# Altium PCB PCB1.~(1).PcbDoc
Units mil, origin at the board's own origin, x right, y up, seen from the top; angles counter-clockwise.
Board outline 4980 x 2750 mil, 2 copper layers (Top Layer, Bottom Layer); 145 components, 200 nets, 610 pads, 29 vias.
Unrouted connection lines stored in the file: 204.
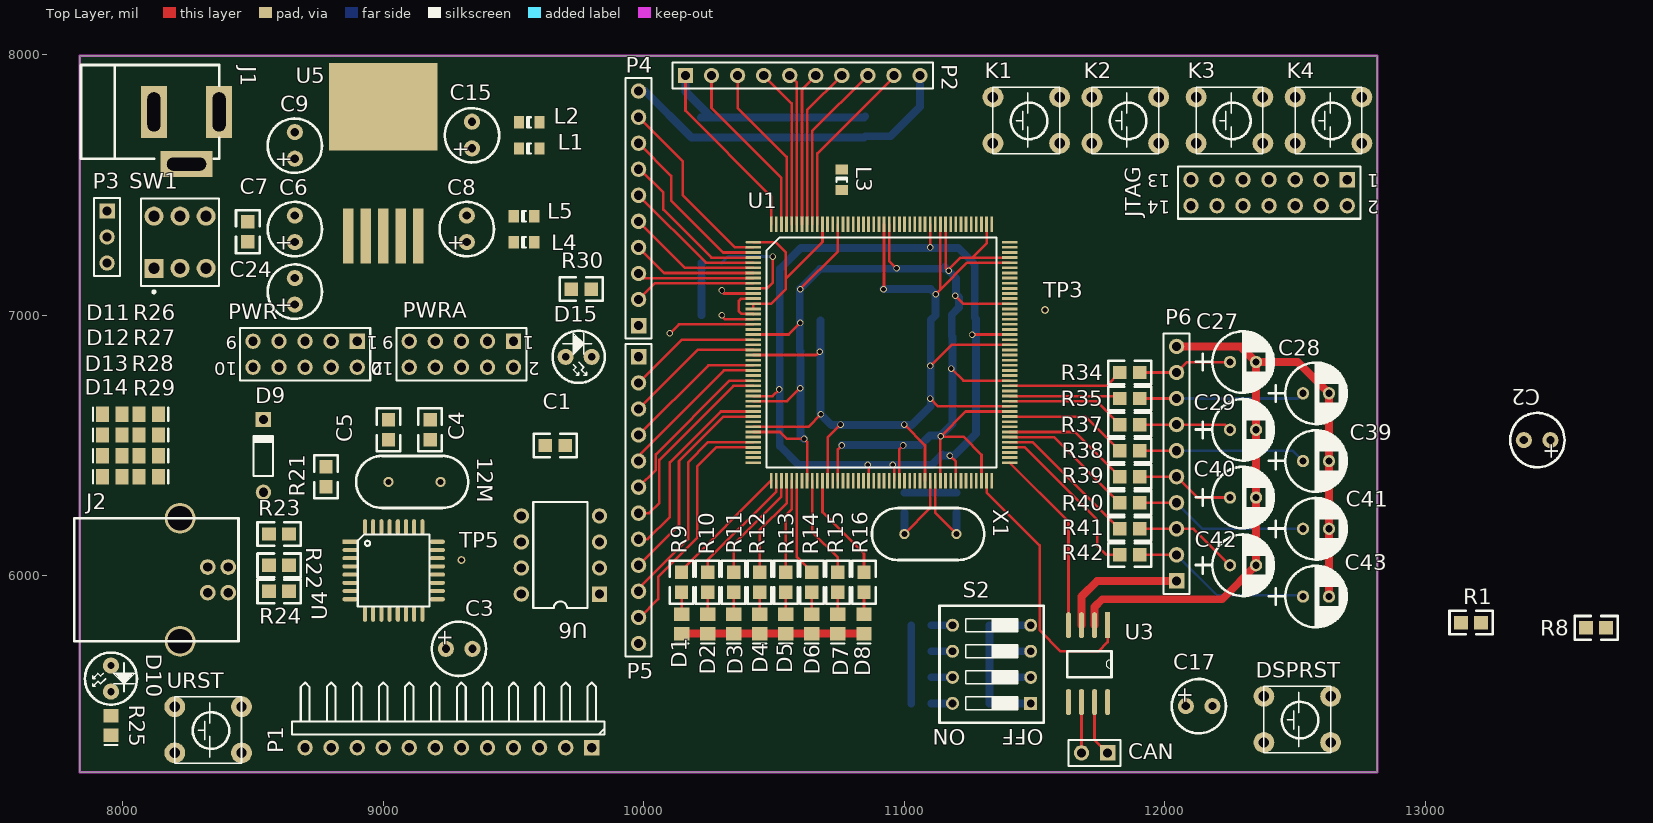
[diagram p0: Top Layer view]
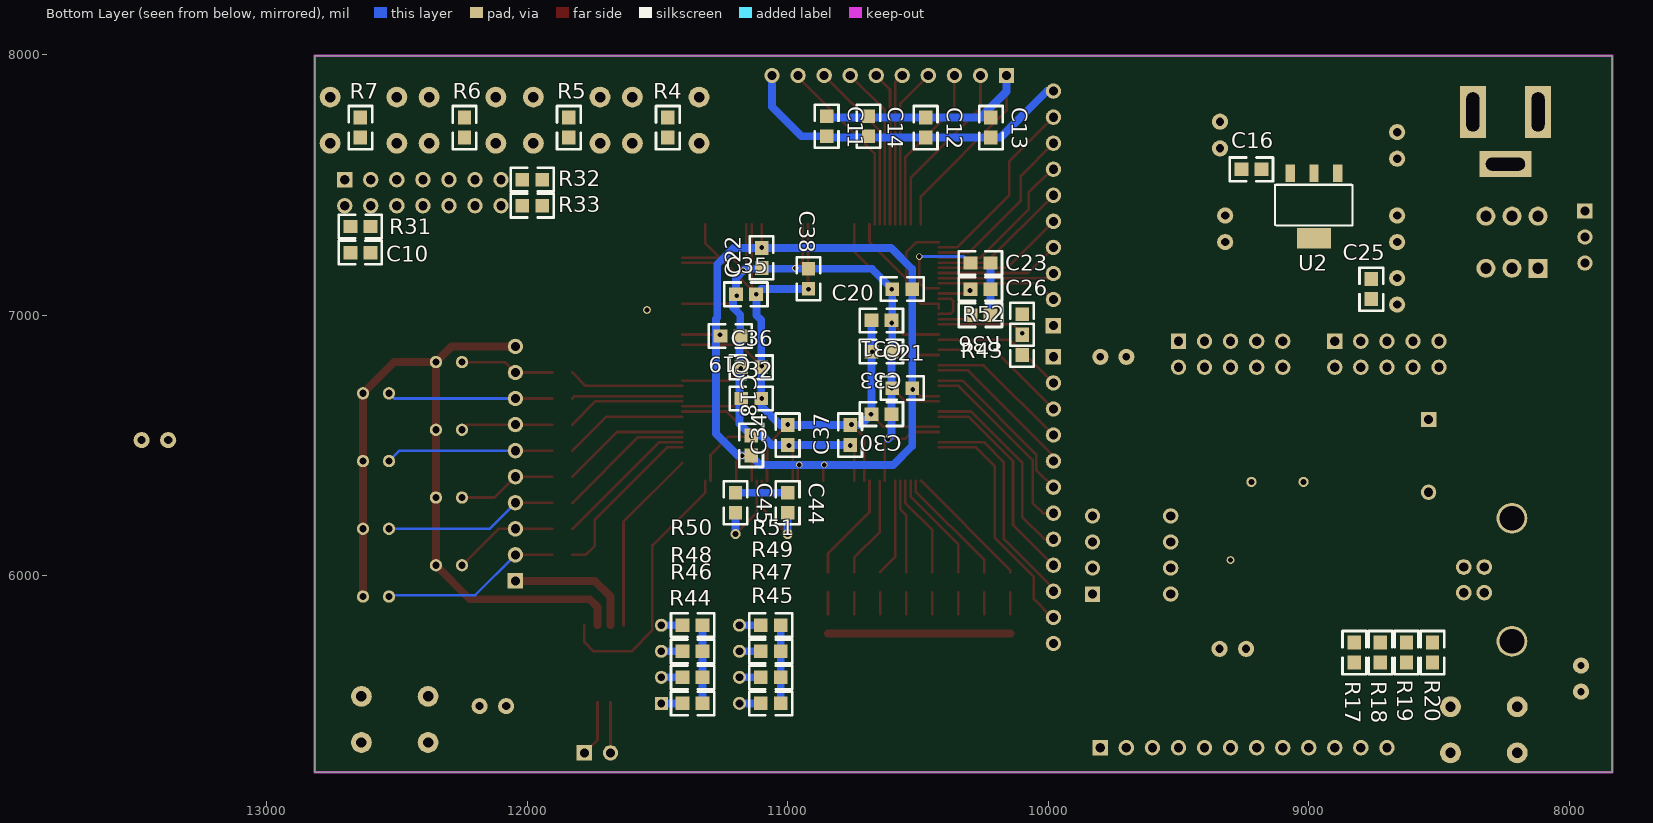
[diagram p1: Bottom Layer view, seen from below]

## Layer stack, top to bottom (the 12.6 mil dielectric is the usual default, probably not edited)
Top Layer: signal copper 1.4
Dielectric: core 12.6, FR-4, Dk 4.8
Bottom Layer: signal copper 1.4

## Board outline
7835,7995 7835,5245 12815,5245 12815,7995

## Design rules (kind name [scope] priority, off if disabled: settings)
Clearance [All] p1: gap=4
ComponentClearance [All] p1: gap=0 collisioncheckmode=3 verticalgap=0 showdistances=FALSE
HoleSize [All] p1: absolutevalues=TRUE maxlimit=1000 minlimit=0 maxpercent=80.000 minpercent=20.000
HoleToHoleClearance [All] p1: gap=1 allowstackedmicrovias=TRUE
MinimumSolderMaskSliver [All] p1: minsoldermaskwidth=2
PlaneClearance [All] p1: clearance=1
PlaneConnect [All] p1: planeconnectstyle=Direct reliefexpansion=20 reliefentries=4 reliefconductorwidth=10 reliefairgap=10
PolygonConnect [All] p1: connectstyle=Direct reliefconductorwidth=10 reliefentries=4 polygonreliefangle="90 Angle"
RoutingCorners [All] p1: cornerstyle=45-Degree minsetback=0 maxsetback=100
RoutingTopology [All] p1: topology=Horizontal
RoutingVias [All] p1: holewidth=18 width=25 viastyle="Through Hole" minholewidth=18 minwidth=25 maxholewidth=18 maxwidth=25
SilkToSilkClearance [All] p1: silktosilkclearance=0
SilkscreenOverComponentPads [All] p1: minsilkscreentomaskgap=0
SolderMaskExpansion [All] p1: expansion=2
TestPointUsage [All] p1: valid=0 allowmultiple=FALSE
Testpoint [All] p1: side=15 testpointundercomponent=TRUE minsize=40 maxsize=100 preferedsize=60 minholesize=0 maxholesize=40 preferedholesize=32 testpointgrid=1 style=1021 order=0-112345678
Width [All] p1: maxlimit=50 minlimit=10 preferedwidth=20
14 further rules are at their usual default settings.

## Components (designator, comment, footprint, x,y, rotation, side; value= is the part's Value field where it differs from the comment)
12M "XTAL" GJA-M 9120,6360 r0 top
C1 "Cap" C0805#1 9660,6500 r0 top
C2 "Cap Pol1" C5.3 13480,6520 r180 top
C3 "Cap Pol1" C5.3 9240,5720 r0 top
C4 "Cap" C0805#1 9180,6560 r90 top
C5 "Cap" C0805#1 9020,6560 r90 top
C6 "Cap Pol1" C5.3 8660,7280 r90 top
C7 "Cap" C0805#1 8480,7320 r270 top
C8 "Cap Pol1" C5.3 9320,7280 r90 top
C9 "Cap Pol1" C5.3 8660,7600 r90 top
C10 "Cap" C0805#1 12640,7240 r180 bottom
C11 "Cap" C0805#1 10850,7725 r270 bottom
C12 "Cap" C0805#1 10470,7720 r270 bottom
C13 "Cap" C0805#1 10220,7720 r270 bottom
C14 "Cap" C0805#1 10690,7725 r270 bottom
C15 "Cap Pol1" C5.3 9340,7640 r90 top
C16 "Cap" C0805#1 9220,7560 r180 bottom
C17 "Cap Pol1" C5.3 12080,5500 r0 top
C18 "Cap" C0805#1 11140,6500 r270 bottom
C19 "Cap" C0805#1 11220,6920 r0 bottom
C20 "Cap" C0805#1 10560,7100 r180 bottom
C21 "Cap" C0805#1 10560,6720 r180 bottom
C22 "Cap" C0805#1 11100,7220 r90 bottom
C23 "Cap" C0805#1 10260,7200 r180 bottom
C24 "Cap Pol1" C5.3 8660,7040 r90 top
C25 "Cap" C0805#1 8760,7100 r270 bottom
C26 "Cap" C0805#1 10260,7100 r180 bottom
C27 "Cap Pol2" CE2/6/.5 12300,6820 r90 top
C28 "Cap Pol2" CE2/6/.5 12580,6700 r90 top
C29 "Cap Pol2" CE2/6/.5 12300,6560 r90 top
C30 "Cap" C0805#1 10640,6620 r0 bottom
C31 "Cap" C0805#1 10640,6980 r0 bottom
C32 "Cap" C0805#1 11140,6680 r180 bottom
C33 "Cap" C0805#1 10640,6860 r0 bottom
C34 "Cap" C0805#1 11000,6540 r90 bottom
C35 "Cap" C0805#1 11160,7080 r180 bottom
C36 "Cap" C0805#1 11140,6800 r180 bottom
C37 "Cap" C0805#1 10760,6540 r90 bottom
C38 "Cap" C0805#1 10920,7140 r270 bottom
C39 "Cap Pol2" CE2/6/.5 12580,6440 r90 top
C40 "Cap Pol2" CE2/6/.5 12300,6300 r90 top
C41 "Cap Pol2" CE2/6/.5 12580,6180 r90 top
C42 "Cap Pol2" CE2/6/.5 12300,6040 r90 top
C43 "Cap Pol2" CE2/6/.5 12580,5920 r90 top
C44 "Cap" C0805#1 11000,6280 r270 bottom
C45 "Cap" C0805#1 11200,6280 r270 bottom
CAN "Header 2" HDR1X2 11780,5320 r180 top
D1 "LED1" C0805#2 10145,5815 r90 top
D2 "LED1" C0805#2 10245,5815 r90 top
D3 "LED1" C0805#2 10345,5815 r90 top
D4 "LED1" C0805#2 10445,5815 r90 top
D5 "LED1" C0805#2 10545,5815 r90 top
D6 "LED1" C0805#2 10645,5815 r90 top
D7 "LED1" C0805#2 10745,5815 r90 top
D8 "LED1" C0805#2 10845,5815 r90 top
D9 "1N4148" DO-35 8540,6460 r90 top
D10 "LED1" LED 7955,5655 r270 top
D11 "LED1" C0805#2 7960,6620 r0 top
D12 "LED1" C0805#2 7960,6540 r0 top
D13 "LED1" C0805#2 7960,6460 r0 top
D14 "LED1" C0805#2 7960,6380 r0 top
D15 "LED1" LED 9700,6840 r0 top
DSPRST "Button" SW-6 12380,5360 r0 top
J1 "PWR2.5" DCJACK 8120,7780 r0 top
J2 "USB_B_Female" USB_B_Female 8220,5980 r0 top
JTAG "JTAG14" HDR2X7 12700,7520 r180 top
K1 "Button" SW-6 11340,7660 r0 top
K2 "Button" SW-6 11720,7660 r0 top
K3 "Button" SW-6 12120,7660 r0 top
K4 "Button" SW-6 12500,7660 r0 top
L1 "Inductor" 2029 9560,7640 r0 top
L2 "Inductor" 2029 9560,7740 r0 top
L3 "Inductor" 2029 10760,7520 r270 top
L4 "Inductor" 2029 9540,7280 r0 top
L5 "Inductor" 2029 9540,7380 r0 top
P1 "Header 12H" HDR1X12H 9800,5340 r180 top
P2 "Header 10" HDR1X10 10160,7920 r0 top
P3 "Header 3" HDR1X3 7940,7400 r270 top
P4 "Header 10" HDR1X10 9980,6960 r90 top
P5 "Header 12" HDR1X12 9980,6840 r270 top
P6 "Header 10" HDR1X10 12045,5980 r90 top
PWR "Header 5X2" HDR2X5 8900,6900 r180 top
PWRA "Header 5X2" HDR2X5 9500,6900 r180 top
R1 "Res2" c0805 13175,5820 r0 top
R4 "Res2" c0805 11460,7720 r90 bottom
R5 "Res2" c0805 11840,7720 r90 bottom
R6 "Res2" c0805 12240,7720 r90 bottom
R7 "Res2" c0805 12640,7720 r270 bottom
R8 "Res2" c0805 13655,5800 r0 top
R9 "Res2" c0805 10145,5975 r270 top
R10 "Res2" c0805 10245,5975 r270 top
R11 "Res2" c0805 10345,5975 r270 top
R12 "Res2" c0805 10445,5975 r270 top
R13 "Res2" c0805 10545,5975 r270 top
R14 "Res2" c0805 10645,5975 r270 top
R15 "Res2" c0805 10745,5975 r270 top
R16 "Res2" c0805 10845,5975 r270 top
R17 "Res2" c0805 8825,5705 r270 bottom
R18 "Res2" c0805 8725,5705 r270 bottom
R19 "Res2" c0805 8625,5705 r270 bottom
R20 "Res2" c0805 8525,5705 r270 bottom
R21 "Res2" c0805 8780,6380 r90 top
R22 "Res2" c0805 8600,6040 r180 top
R23 "Res2" c0805 8600,6160 r180 top
R24 "Res2" c0805 8600,5940 r180 top
R25 "Res1" C0805#2 7955,5425 r90 top
R26 "Res1" C0805#2 8100,6620 r180 top
R27 "Res1" C0805#2 8100,6540 r180 top
R28 "Res1" C0805#2 8100,6460 r180 top
R29 "Res1" C0805#2 8100,6380 r180 top
R30 "Res2" c0805 9760,7100 r0 top
R31 "Res2" c0805 12640,7340 r0 bottom
R32 "Res2" c0805 11980,7520 r0 bottom
R33 "Res2" c0805 11980,7420 r0 bottom
R34 "Res2" c0805 11865,6780 r0 top
R35 "Res2" c0805 11865,6680 r0 top
R36 "Res2" c0805 10260,7000 r0 bottom
R37 "Res2" c0805 11865,6580 r0 top
R38 "Res2" c0805 11865,6480 r0 top
R39 "Res2" c0805 11865,6380 r0 top
R40 "Res2" c0805 11865,6280 r0 top
R41 "Res2" c0805 11865,6180 r0 top
R42 "Res2" c0805 11865,6080 r0 top
R43 "Res2" c0805 10100,6885 r270 bottom
R44 "Res2" c0805 11365,5510 r0 bottom
R45 "Res2" c0805 11065,5510 r180 bottom
R46 "Res2" c0805 11365,5610 r0 bottom
R47 "Res2" c0805 11065,5610 r180 bottom
R48 "Res2" c0805 11365,5710 r0 bottom
R49 "Res2" c0805 11065,5710 r180 bottom
R50 "Res2" c0805 11365,5810 r0 bottom
R51 "Res2" c0805 11065,5810 r180 bottom
R52 "Res2" c0805 10100,6965 r270 bottom
S2 "SW SO8" SW-DIP2x4 11485,5510 r180 top
SW1 "SWITCH" DPDT-6 8220,7280 r90 top
TP3 "TestPoint" TESTPOINT 11540,7020 r90 top
TP5 "TestPoint" TESTPOINT 9300,6060 r90 top
U1 "TMS320F2812" Quad176_2812 10420,7280 r0 top
U2 "AS1117-1.8" SOT-223 8980,7420 r0 bottom
U3 "SN65HVD232" SOP8 11720,5660 r270 top
U4 "TUSB3410" DMC68HC908JL8 9040,6020 r90 top
U5 "TPS78633" PSFM_G5 9000,7800 r0 top
U6 "24LCxx" DIP-8 9680,6080 r90 top
URST "Button" SW-6 8200,5320 r0 top
X1 "30MHz" GJA-M 11100,6160 r0 top

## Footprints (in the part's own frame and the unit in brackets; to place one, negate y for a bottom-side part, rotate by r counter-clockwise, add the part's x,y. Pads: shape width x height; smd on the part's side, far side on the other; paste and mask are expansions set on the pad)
2029 [mm] "Chip Inductor; Body 2 x 1.2 mm (LxW typ)"
  rect 1x1.2 smd: 1(-1,0) 2(1,0)
  silkscreen extent -0.2,-0.5 0.2,0.5
C5.3 [mil]
  round 62 hole 31.5: 1(0.39,-0.55) 2(102.39,-0.55)
  silkscreen extent -54,-105 155,104
C0805#1 [mm]
  rect 1.35x1.3 smd: 1(-0.975,0) 2(0.975,0)
  silkscreen extent -2.1,-1.15 2.1,1.15
C0805#2 [mm] "Chip Capacitor; Body 2.0 x 1.2 mm (LxW typ)"
  rect 1.3x1.5 smd: 1(-0.95,0) 2(0.95,0)
  silkscreen extent -1.9,-0.65 -1.9,0.65
c0805 [mm]
  rect 1.35x1.3 smd: 1(-0.975,0) 2(0.975,0)
  silkscreen extent -2.1,-1.15 2.1,1.15
CE2/6/.5 [mm]
  round 1.2 hole 0.7: 1(0,1.27) 2(0,-1.27)
  silkscreen extent -3,-3 3,4.62
DCJACK [mil]
  rect 100x200 hole 50 slot 150 at 90 deg: 1(0,0) 2(250,0)
  rect 200x100 hole 50 slot 150 at 0 deg: 3(125,-200)
  silkscreen extent -280,-180 250,180
DIP-8 [mm]
  rect 1.5x1.5 hole 0.9: 1(-3.822,-3.81)
  round 1.5 hole 0.9: 2(-1.282,-3.81) 3(1.258,-3.81) 4(3.798,-3.81) 5(3.798,3.81) 6(1.258,3.81) 7(-1.282,3.81) 8(-3.822,3.81)
  silkscreen extent -5.16,-2.65 5.14,2.65
DMC68HC908JL8 [mm]
  rect 0.4x1.5 smd: 1(2.8,4.25)
  oval 0.4x1.5 smd: 2(2,4.25) 3(1.2,4.25) 4(0.4,4.25) 5(-0.4,4.25) 6(-1.2,4.25) 7(-2,4.25) 8(-2.8,4.25) 17(-2.8,-4.25) 18(-2,-4.25) 19(-1.2,-4.25) 20(-0.4,-4.25) 21(0.4,-4.25) 22(1.2,-4.25) 23(2,-4.25) 24(2.8,-4.25)
  oval 1.5x0.4 smd: 9(-4.25,2.8) 10(-4.25,2) 11(-4.25,1.2) 12(-4.25,0.4) 13(-4.25,-0.4) 14(-4.25,-1.2) 15(-4.25,-2) 16(-4.25,-2.8) 25(4.25,-2.8) 26(4.25,-2) 27(4.25,-1.2) 28(4.25,-0.4) 29(4.25,0.4) 30(4.25,1.2) 31(4.25,2) 32(4.25,2.8)
  silkscreen extent -3.5,-3.5 3.5,3.5
DO-35 [mm] "Diode, Axial; Body 3.8 x 1.9 mm (LxDia. max), Lead Dia. 0.53 mm (max)"
  round 1.5 hole 0.9: 1(-3.55,0)
  rect 1.5x1.5 hole 0.9: 2(3.55,0)
  silkscreen extent -1.95,-0.95 2.05,0.95
DPDT-6 [mm] "Double-Pole, Double-Throw Switch; 6 Leads"
  rect 1.85x1.85 hole 1.1: 1(-2.54,2.54)
  round 1.85 hole 1.1: 2(-2.54,0) 3(-2.54,-2.54) 4(2.54,-2.54) 5(2.54,0) 6(2.54,2.54)
  silkscreen extent -4.96,-3.81 4.28,3.81
GJA-M [mm]
  round 1 hole 0.6: 1(-2.54,0) 2(2.54,0)
  silkscreen extent -5.69,-2.54 5.23,2.54
HDR1X2 [mm] "Connector; Header; 2 Position"
  rect 1.5x1.5 hole 0.9: 1(0,0)
  round 1.5 hole 0.9: 2(2.54,0)
  silkscreen extent -1.27,-1.27 3.81,1.27
HDR1X3 [mm] "Connector; Header; 3 Position"
  rect 1.5x1.5 hole 0.9: 1(0,0)
  round 1.5 hole 0.9: 2(2.54,0) 3(5.08,0)
  silkscreen extent -1.27,-1.27 6.35,1.27
HDR1X10 [mm] "Connector; Header; 10 Position"
  rect 1.5x1.5 hole 0.9: 1(0,0)
  round 1.5 hole 0.9: 2(2.54,0) 3(5.08,0) 4(7.62,0) 5(10.16,0) 6(12.7,0) 7(15.24,0) 8(17.78,0) 9(20.32,0) 10(22.86,0)
  silkscreen extent -1.27,-1.27 24.13,1.27
HDR1X12 [mm] "Connector; Header; 12 Position"
  rect 1.5x1.5 hole 0.9: 1(0,0)
  round 1.5 hole 0.9: 2(2.54,0) 3(5.08,0) 4(7.62,0) 5(10.16,0) 6(12.7,0) 7(15.24,0) 8(17.78,0) 9(20.32,0) 10(22.86,0) 11(25.4,0) 12(27.94,0)
  silkscreen extent -1.27,-1.27 29.21,1.27
HDR1X12H [mm] "Connector; Header; 12 Position; Right Angle"
  rect 1.5x1.5 hole 0.9: 1(0,0)
  round 1.5 hole 0.9: 2(2.54,0) 3(5.08,0) 4(7.62,0) 5(10.16,0) 6(12.7,0) 7(15.24,0) 8(17.78,0) 9(20.32,0) 10(22.86,0) 11(25.4,0) 12(27.94,0)
  silkscreen extent -1.27,-6.35 29.21,-1.27
HDR2X5 [mm] "Connector; Header; 5x2 Position"
  rect 1.5x1.5 hole 0.9: 1(0,0)
  round 1.5 hole 0.9: 2(0,2.54) 3(2.54,0) 4(2.54,2.54) 5(5.08,0) 6(5.08,2.54) 7(7.62,0) 8(7.62,2.54) 9(10.16,0) 10(10.16,2.54)
  silkscreen extent -1.27,-1.27 11.43,3.81
HDR2X7 [mm] "Connector; Header; 7x2 Position"
  rect 1.5x1.5 hole 0.9: 1(0,0)
  round 1.5 hole 0.9: 2(0,2.54) 3(2.54,0) 4(2.54,2.54) 5(5.08,0) 6(5.08,2.54) 7(7.62,0) 8(7.62,2.54) 9(10.16,0) 10(10.16,2.54) 11(12.7,0) 12(12.7,2.54) 13(15.24,0) 14(15.24,2.54)
  silkscreen extent -1.27,-1.27 16.51,3.81
LED [mil]
  round 62 hole 28: 1(0,0) 2(100,0)
  silkscreen extent -50,-100 150,100
PSFM_G5 [mm]
  rect 1x5.4 smd: 1(-3.4,-12.6) 2(-1.7,-12.6) 3(0,-12.6) 4(1.7,-12.6) 5(3.4,-12.6)
  rect 10.6x8.5 smd: 6(0,0)
Quad176_2812 [mm]
  oval 1.5x0.27 smd: 1(0,0)
  rect 1.5x0.27 smd: 2(0,-0.5) 3(0,-1) 4(0,-1.5) 5(0,-2) 6(0,-2.5) 7(0,-3) 8(0,-3.5) 9(0,-4) 10(0,-4.5) 11(0,-5) 12(0,-5.5) 13(0,-6) 14(0,-6.5) 15(0,-7) 16(0,-7.5) 17(0,-8) 18(0,-8.5) 19(0,-9) 20(0,-9.5) 21(0,-10) 22(0,-10.5) 23(0,-11) 24(0,-11.5) 25(0,-12) 26(0,-12.5) 27(0,-13) 28(0,-13.5) 29(0,-14) 30(0,-14.5) 31(0,-15) 32(0,-15.5) 33(0,-16) 34(0,-16.5) 35(0,-17) 36(0,-17.5) 37(0,-18) 38(0,-18.5) 39(0,-19) 40(0,-19.5) 41(0,-20) 42(0,-20.5) 43(0,-21) 44(0,-21.5) 89(25,-21.5) 90(25,-21) 91(25,-20.5) 92(25,-20) 93(25,-19.5) 94(25,-19) 95(25,-18.5) 96(25,-18) 97(25,-17.5) 98(25,-17) 99(25,-16.5) 100(25,-16) 101(25,-15.5) 102(25,-15) 103(25,-14.5) 104(25,-14) 105(25,-13.5) 106(25,-13) 107(25,-12.5) 108(25,-12) 109(25,-11.5) 110(25,-11) 111(25,-10.5) 112(25,-10) 113(25,-9.5) 114(25,-9) 115(25,-8.5) 116(25,-8) 117(25,-7.5) 118(25,-7) 119(25,-6.5) 120(25,-6) 121(25,-5.5) 122(25,-5) 123(25,-4.5) 124(25,-4) 125(25,-3.5) 126(25,-3) 127(25,-2.5) 128(25,-2) 129(25,-1.5) 130(25,-1) 131(25,-0.5) 132(25,0)
  rect 0.27x1.5 smd: 45(1.75,-23.25) 46(2.25,-23.25) 47(2.75,-23.25) 48(3.25,-23.25) 49(3.75,-23.25) 50(4.25,-23.25) 51(4.75,-23.25) 52(5.25,-23.25) 53(5.75,-23.25) 54(6.25,-23.25) 55(6.75,-23.25) 56(7.25,-23.25) 57(7.75,-23.25) 58(8.25,-23.25) 59(8.75,-23.25) 60(9.25,-23.25) 61(9.75,-23.25) 62(10.25,-23.25) 63(10.75,-23.25) 64(11.25,-23.25) 65(11.75,-23.25) 66(12.25,-23.25) 67(12.75,-23.25) 68(13.25,-23.25) 69(13.75,-23.25) 70(14.25,-23.25) 71(14.75,-23.25) 72(15.25,-23.25) 73(15.75,-23.25) 74(16.25,-23.25) 75(16.75,-23.25) 76(17.25,-23.25) 77(17.75,-23.25) 78(18.25,-23.25) 79(18.75,-23.25) 80(19.25,-23.25) 81(19.75,-23.25) 82(20.25,-23.25) 83(20.75,-23.25) 84(21.25,-23.25) 85(21.75,-23.25) 86(22.25,-23.25) 87(22.75,-23.25) 88(23.25,-23.25) 133(23.25,1.75) 134(22.75,1.75) 135(22.25,1.75) 136(21.75,1.75) 137(21.25,1.75) 138(20.75,1.75) 139(20.25,1.75) 140(19.75,1.75) 141(19.25,1.75) 142(18.75,1.75) 143(18.25,1.75) 144(17.75,1.75) 145(17.25,1.75) 146(16.75,1.75) 147(16.25,1.75) 148(15.75,1.75) 149(15.25,1.75) 150(14.75,1.75) 151(14.25,1.75) 152(13.75,1.75) 153(13.25,1.75) 154(12.75,1.75) 155(12.25,1.75) 156(11.75,1.75) 157(11.25,1.75) 158(10.75,1.75) 159(10.25,1.75) 160(9.75,1.75) 161(9.25,1.75) 162(8.75,1.75) 163(8.25,1.75) 164(7.75,1.75) 165(7.25,1.75) 166(6.75,1.75) 167(6.25,1.75) 168(5.75,1.75) 169(5.25,1.75) 170(4.75,1.75) 171(4.25,1.75) 172(3.75,1.75) 173(3.25,1.75) 174(2.75,1.75) 175(2.25,1.75) 176(1.75,1.75)
  silkscreen extent 1.28,-21.96 23.71,0.47
SOP8 [mil]
  rect 100x20 smd: 1(-150,60)
  oval 100x20 smd: 2(-150,10) 3(-150,-40) 4(-150,-90) 5(145,-90) 6(145,-40) 7(145,10) 8(145,60)
  silkscreen extent -50,-95 50,75
SOT-223 [mm]
  rect 0.9x1.7 smd: 1(-2.311,-3.162) 2(0,-3.162) 3(2.311,-3.162)
  rect 3.28x2 smd: 4(0,3.162)
  silkscreen extent -3.76,-2.07 3.78,1.92
SW-6 [mil]
  round 80 hole 40: 1(0,0) 2(0,177) 3(256,0) 4(256,177)
  silkscreen extent 0,-40 256,215
SW-DIP2x4 [mil]
  rect 50x50 hole 30: 1(0,0)
  round 50 hole 30: 2(0,-100) 3(0,-200) 4(0,-300) 5(300,-300) 6(300,-200) 7(300,-100) 8(300,0)
  silkscreen extent -50,-375 350,75
TESTPOINT [mil]
  round 30 hole 20: 1(0,0)
USB_B_Female [mil]
  round 60 hole 36.22: 1(185,-45) 2(185,53.42) 3(106.26,53.42) 4(106.26,-45)
  round 118.11 hole 94.49: 5(-0.04,240.43) 6(-0.04,-232.01)
  silkscreen extent -406,-232 224,240

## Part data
12M: "Crystal Oscillator"
C1 C5: library part "Cap Pol1", "Polarized Capacitor (Radial)"
C2 C6 C8 C27 C28 C29 C39: library part Cap, "Capacitor"
C3 C15 C17 C24: "Polarized Capacitor (Radial)"
C4 C7 C10 C11 C12 C13 C14 C16 C18 C19 C20 C21 C22 C23 C25 C26 C30 C31 C32 C33 C34 C35 C36 C37 C38 C44 C45: "Capacitor"
C9: library part CAP, "Capacitor"
C40 C41 C42 C43: "Polarized Capacitor (Axial)"
CAN: "Header, 2-Pin"
D1 D2 D3 D4 D5 D6 D7 D8 D10 D11 D12 D13 D14 D15: "Typical RED GaAs LED"
D9: library part "Diode 1N4148", "High Conductance Fast Diode"
DSPRST K1 K2 K3 K4 URST: library part Button_4
J1: "Low Voltage Power Supply Connector"
JTAG: library part "Header 7X2", "Header, 7-Pin, Dual row"
P1: "Header, 12-Pin, Right Angle"
P2 P4 P6: "Header, 10-Pin"
P3: "Header, 3-Pin"
P5: library part "Header 8", "Header, 8-Pin"
PWR PWRA: "Header, 5-Pin, Dual row"
R1 R4 R5 R6 R9 R10 R11 R12 R13 R14 R15 R16 R17 R18 R19 R20 R21 R22 R23 R24 R25 R26 R27 R28 R29 R30 R31 R32 R33 R34 R35 R36 R37 R38 R39 R40 R41 R42 R43 R44 R45 R46 R47 R48 R49 R50 R51 R52: "Resistor"
R7 R8: library part RES2
S2: library part "SW DIP-4", "DIP Switch"
SW1: library part SW-DPDT
TP3 TP5: "TespPoint"
U2: library part TPS767D318
U3: "CAN transmiceiver"
U5: library part CY7C1041V33
U6: library part MAX3232
X1: library part CRYSTAL

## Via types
v1: diameter 25, hole 18, Top Layer to Bottom Layer, 29 vias

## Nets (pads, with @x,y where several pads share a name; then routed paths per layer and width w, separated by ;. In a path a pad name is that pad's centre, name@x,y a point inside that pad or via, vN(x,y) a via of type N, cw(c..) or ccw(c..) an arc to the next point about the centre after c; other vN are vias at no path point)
+1.8: C30.2 C31.2 C32.2 C33.2 C34.2 C35.2 C36.2 C37.2 C38.2 L3.1 U1.23 U1.37 U1.56 U1.75 U1.100 U1.112 U1.128 U1.143 U1.154 | length 3991.9
  Top Layer w10: U1.37 10631.34,6571.34 v1(10680,6620) ; U1.23 10661.93,6846.93 v1(10675,6860) ; U1.56 10705.43,6530.43 v1(10755,6580) ; v1(10920,7100) 10921.97,7101.97 U1.154 ; v1(11000,6580) 11079.45,6500.55 U1.75 ; v1(11100,6680) 11129.92,6650.08 U1.100 ; v1(11100,6805) 11181.3,6886.3 U1.112 ; v1(11120,7080) 11138.5,7098.5 ; U1.143 11138.5,7098.5 ; U1.128 11241.26,7201.26 11138.5,7098.5
  Bottom Layer w30: C31.2 C33.2 C30.2 10720,6578.39 11028.39,6578.39 11101.61,6651.61 11101.61,6981.61 11120,7000 11120,7078.39 C35.2 11101.61,7100 10921.61,7100 C38.2
+1.8V: C24.1 C25.2 U2.2 U2.4 U4.4
+3.3: C1.2 C8.1 C15.1 C16.2 D11.1 D12.1 D13.1 D14.1 L1.1 L4.1 P1.1 R17.2 R18.2 R19.2 R20.2 R30.1 U2.3 U4.3 U4.23 U4.24 U4.25 U5.4 U6.8
+5: C6.1 C7.2 SW1.1 SW1.6 U5.1 U5.2
ADA0: P2.2 U1.174 | length 682.2
  Top Layer w10: P2.2 10260,7795 10528.27,7526.73 U1.174
ADA1: P2.3 U1.173 | length 649
  Top Layer w10: P2.3 10360,7795 10547.95,7607.05 U1.173
ADA2: P2.4 U1.172 | length 615.7
  Top Layer w10: P2.4 10567.64,7812.36 U1.172
ADA3: P2.5 U1.171 | length 582.4
  Top Layer w10: P2.5 10587.32,7892.68 U1.171
ADA4: P2.6 U1.170 | length 593.1
  Top Layer w10: U1.170 10607.01,7867.01 P2.6
ADA5: P2.7 U1.169 | length 626.3
  Top Layer w10: U1.169 10626.69,7786.69 P2.7
ADA6: P2.8 U1.168 | length 659.6
  Top Layer w10: U1.168 10646.38,7706.38 P2.8
ADA7: P2.9 U1.167 | length 692.9
  Top Layer w10: U1.167 10666.06,7621.06 10960,7915 P2.9
ADB0: P4.9 U1.2 | length 723.1
  Top Layer w10: P4.9 10012.5,7727.5 10150,7590 10150,7460 10349.68,7260.32 U1.2
ADB1: P4.8 U1.3 | length 669.4
  Top Layer w10: P4.8 10105,7535 10105,7440 10304.37,7240.63 U1.3
ADB2: P4.7 U1.4 | length 618.5
  Top Layer w10: P4.7 9985,7560 10075,7470 10075,7405 10259.05,7220.95 U1.4
ADB3: P4.6 U1.5 | length 547.2
  Top Layer w10: P4.6 10238.74,7201.26 U1.5
ADB4: P4.5 U1.6 | length 513.9
  Top Layer w10: P4.5 10158.42,7181.58 U1.6
ADB5: P4.4 U1.7 | length 480.6
  Top Layer w10: P4.4 10078.11,7161.89 U1.7
ADB6: P4.3 U1.8 | length 447.4
  Top Layer w10: P4.3 9997.79,7142.21 U1.8
ADB7: P4.2 U1.9 | length 465.9
  Top Layer w10: P4.2 10042.52,7122.52 U1.9
CTS: P1.9 U4.13
DA1: C43.1 P6.2 R42.2 | length 692.9
  Top Layer w10: R42.2 P6.2
  Bottom Layer w10: P6.2 12200,5925 12525,5925 C43.1
DA2: C42.1 P6.3 R41.2 | length 404.6
  Top Layer w10: R41.2 P6.3 12110,6180 C42.1
DA3: C41.1 P6.4 R40.2 | length 668
  Top Layer w10: R40.2 P6.4
  Bottom Layer w10: P6.4 12145,6180 C41.1
DA4: C40.1 P6.5 R39.2 | length 379.8
  Top Layer w10: R39.2 P6.5 12125,6300 C40.1
DA5: C39.1 P6.6 R38.2 | length 643.2
  Top Layer w10: R38.2 P6.6
  Bottom Layer w10: P6.6 12490,6480 C39.1
DA6: C29.1 P6.7 R37.2 | length 354.9
  Top Layer w10: R37.2 P6.7 12230,6580 C29.1
DA7: C28.1 P6.8 R35.2 | length 634.9
  Top Layer w10: R35.2 P6.8
  Bottom Layer w10: P6.8 12510,6680 C28.1
DA8: C27.1 P6.9 R34.2 | length 363.2
  Top Layer w10: R34.2 P6.9 12085,6820 C27.1
DCD: P1.7 U4.15
DSP_VDD: C17.1 C18.2 C19.2 C20.2 C21.2 C22.2 D1.1 D2.1 D3.1 D4.1 D5.1 D6.1 D7.1 D8.1 JTAG.5 L1.2 P5.1 P6.1 PWR.1 PWR.3 PWR.5 PWR.7 PWR.9 R1.2 R4.2 R5.2 R6.2 R7.2 R32.1 R33.1 U1.31 U1.64 U1.69 U1.81 U1.114 U1.145 U3.3 | length 4752.2
  Top Layer w10: U1.31 10494.45,6689.45 v1(10520,6715) ; v1(10860,6425) 10862.91,6422.09 U1.64 ; v1(10955,6425) 10955,6420 10961.34,6413.66 U1.69 ; U1.145 11099.13,7260.87 v1(11100,7260) ; v1(11175,6460) 11197.56,6437.44 U1.81 ; v1(11260,6925) 11260.67,6925.67 U1.114
  Top Layer w30: D1.1 D2.1 D3.1 D4.1 D5.1 D6.1 D7.1 D8.1 ; U3.3 11680,5920 11740,5980 P6.1
  Bottom Layer w30: C18.2 C18.2@11141.61,6461.61 ; C18.2@11145,6465 C18.2@11141.61,6461.61 ; C18.2@11141.61,6461.61 11191.61,6461.61 11275,6545 11275,6985 11270,6990 11270,7195 11206.61,7258.39 C22.2 10820,7258.39 10603.39,7258.39 10521.61,7176.61 C20.2 C21.2 10521.61,6498.39 10595,6425 11105,6425 C18.2@11141.61,6461.61
DSP_VDDA: C11.2 C12.2 C13.2 C14.2 L4.2 P2.10 P4.10 PWRA.1 PWRA.3 PWRA.5 PWRA.7 PWRA.9 U1.1 U1.13 U1.14 U1.166 | length 2038.8
  Top Layer w10: U1.14 U1.13 10488.78,7043.78 10545,7100 10545,7140.9 ; U1.1 10505,7280 10545,7240 10545,7140.9 ; U1.166 10685.75,7281.64 10545,7140.9
  Bottom Layer w30: P4.10 10005,7860 10183.39,7681.61 C13.2 C12.2 10845,7681.61 C11.2 10946.61,7686.61 11060,7800 P2.10
DSP_VSS: C2.2 C10.2 C17.2 C18.1 C19.1 C20.1 C21.1 C22.1 C27.2 C28.2 C29.2 C30.1 C31.1 C32.1 C33.1 C34.1 C35.1 C36.1 C37.1 C38.1 C39.2 C40.2 C41.2 C42.2 C43.2 C44.1 C45.1 JTAG.4 JTAG.8 JTAG.10 JTAG.12 K1.2 K2.2 K3.2 K4.2 L2.2 P5.12 P6.10 PWR.2 PWR.4 PWR.6 PWR.8 PWR.10 R8.1 R31.1 U1.19 U1.32 U1.38 U1.52 U1.58 U1.70 U1.78 U1.86 U1.99 U1.105 U1.113 U1.120 U1.129 U1.134 U1.142 U1.153 U1.163 U3.2 | length 8802.7
  Top Layer w10: U1.38 10523.34,6551.66 10550,6525 v1(10615,6525) 10626.69,6513.31 U1.52 ; U1.32 10549.77,6669.77 v1(10600,6720) ; U1.19 10555.67,6925.67 v1(10600,6970) ; v1(10600,7100) 10744.8,7244.8 U1.163 ; U1.58 10744.8,6484.8 v1(10760,6500) ; U1.153 10941.65,7208.35 v1(10970,7180) ; U1.70 10981.02,6486.02 v1(10995,6500) ; U1.78 v1@11138.5,6533.5 ; U1.142 11158.19,7181.81 v1(11170,7170) v1@11170,7175.35 ; v1@11175,7180.35 11215.6,7220.95 11260.95,7220.95 ; v1(11180,6795) 11226.49,6748.51 U1.105 ; v1(11195,7075) 11226.22,7043.78 U1.120 ; U1.86 11295.98,6464.02 11226.5,6533.5 v1@11141.5,6533.5 ; U1.134 11315.67,7275.67 11260.95,7220.95 ; U1.99 11235.4,6630.4 v1(11140,6535) ; U1.129 11260.95,7220.95 ; v1@11138.5,6533.5 v1@11141.5,6533.5 ; v1@11138.5,6533.5 v1(11140,6535) ; v1(11140,6535) v1@11141.5,6533.5
  Top Layer w30: U3.2 11730,5880 11760,5910 12220,5910 C42.2 C40.2 C29.2 C27.2 ; P6.10 12290,6880 C27.2 ; C43.2 C41.2 C39.2 C28.2 12510,6820 C27.2
  Bottom Layer w30: v1(10615,6525) 10601.61,6538.39 C30.1 C33.1 10598.39,6863.23 C20.1 10676.77,7178.39 C38.1 11100,7178.39 11148.39,7178.39 11155,7185 v1(11170,7170) 11198.39,7141.61 C35.1 11210,7068.39 11210,7030 11181.61,7001.61 C19.1 11185,6916.61 11185,6583.39 C18.1 11098.39,6538.39 11061.61,6501.61 C34.1 C37.1 ; C44.1 C45.1
DSP_VSSA: C11.1 C12.1 C13.1 C14.1 C23.2 C26.2 L5.2 P2.1 P4.1 PWRA.2 PWRA.4 PWRA.6 PWRA.8 PWRA.10 R36.1 U1.12 U1.15 U1.165 U1.175 U1.176 | length 1900.3
  Top Layer w10: P2.1 10160,7785 10488.9,7456.1 U1.176 ; U1.15 10419.41,7005 10375,7005 10365,7015 10365,7055 10373.47,7063.47 U1.12
  Bottom Layer w30: P2.1 10160,7858.39 10260,7758.39 ; C13.1 10260,7758.39 ; R36.1 C26.2 C23.2 ; C11.1 10845,7758.39 C12.1 10260,7758.39
DSPVDD: R43.2 R44.1 R46.1 R48.1 R50.1 | length 300
  Bottom Layer w30: R44.1 R46.1 11326.61,5730 R50.1
DSPVSS: R45.2 R47.2 R49.2 R51.2 R52.1 | length 300
  Bottom Layer w30: R45.2 R47.2 R49.2 R51.2
DSR: P1.8 U4.14
DTR: P1.5 U4.21
EMU0: JTAG.13 R32.2 U1.137
EMU1: JTAG.14 R33.2 U1.146
GND: C1.1 C3.2 C4.2 C5.2 C6.2 C7.1 C8.2 C9.2 C15.2 C16.1 C24.2 C25.1 D15.2 J1.1 J2.4 L2.1 L5.1 P1.12 R25.1 U2.1 U4.8 U4.18 U4.28 U5.3 U5.6 U6.1 U6.2 U6.3 U6.4 URST.4
GPIOA0: R42.1 U1.92 | length 651.8
  Top Layer w10: U1.92 11462.4,6492.6 11740,6215 11740,6115 11775,6080 R42.1
GPIOA1: R41.1 U1.93 | length 560
  Top Layer w10: U1.93 11492.71,6512.29 11825,6180 R41.1
GPIOA2: R40.1 U1.94 | length 526.7
  Top Layer w10: U1.94 11574.64,6531.97 R40.1
GPIOA3: R39.1 U1.95 | length 493.5
  Top Layer w10: U1.95 11654.96,6551.66 R39.1
GPIOA4: R38.1 U1.98 | length 476.5
  Top Layer w10: U1.98 11695.9,6610.71 R38.1
GPIOA5: R37.1 U1.101 | length 459.5
  Top Layer w10: U1.101 11736.85,6669.77 R37.1
GPIOA6: R35.1 U1.102 | length 426.3
  Top Layer w10: U1.102 11817.16,6689.45 R35.1
GPIOA7: R34.1 U1.104 | length 443.6
  Top Layer w10: U1.104 11775.43,6728.82 R34.1
GPIOA8: U1.106
GPIOA9: U1.107
GPIOA10: U1.109
GPIOA11: U1.116
GPIOA12: U1.117
GPIOA13: U1.122
GPIOA14: U1.123
GPIOA15: U1.124
GPIOB0: R9.1 U1.45 | length 493.7
  Top Layer w10: R9.1 10145,6020.75 U1.45
GPIOB1: R10.1 U1.46 | length 460.4
  Top Layer w10: R10.1 10245,6060 10508.58,6323.58 U1.46
GPIOB2: R11.1 U1.47 | length 427.2
  Top Layer w10: R11.1 10345,6120 10528.27,6303.27 U1.47
GPIOB3: R12.1 U1.48 | length 393.9
  Top Layer w10: R12.1 10445,6175 10547.95,6277.95 U1.48
GPIOB4: R13.1 U1.49 | length 360.6
  Top Layer w10: R13.1 10545,6232.36 10567.64,6255 U1.49
GPIOB5: R14.1 U1.50 | length 375.2
  Top Layer w10: U1.50 10587.32,6071.06 R14.1
GPIOB6: R15.1 U1.53 | length 392.1
  Top Layer w10: U1.53 10646.38,6168.62 10745,6070 R15.1
GPIOB7: R16.1 U1.55 | length 417.2
  Top Layer w10: U1.55 10685.75,6244.25 10845,6085 R16.1
GPIOB8: U1.57
GPIOB9: U1.59
GPIOB10: U1.60
GPIOB11: U1.71
GPIOB12: U1.72
GPIOB13: U1.61
GPIOB14: U1.62
GPIOB15: U1.63
GPIOD0: U1.110
GPIOD1: U1.115
GPIOD5: U1.79
GPIOD6: U1.83
GPIOE0: K3.3 R6.1 U1.149
GPIOE1: K1.3 R4.1 U1.151
GPIOE2: K2.3 R5.1 U1.150
GPIOF0: P5.10 U1.40 | length 855.7
  Top Layer w10: P5.10 9980,5950 10170,6140 10170,6435 10247.29,6512.29 U1.40
GPIOF1: P5.11 U1.41 | length 921.2
  Top Layer w10: P5.11 9985,5840 10055,5910 10055,5995 10205,6145 10205,6420 10277.6,6492.6 U1.41
GPIOF2: P5.8 R44.2 S2.1 U1.34 | length 847.8
  Top Layer w10: P5.8 10015,6140 10100,6225 10100,6435 10295.4,6630.4 U1.34
  Bottom Layer w30: R44.2 S2.1
GPIOF3: P5.9 R46.2 S2.2 U1.35 | length 901.5
  Top Layer w10: P5.9 10135,6195 10135,6440 10305.71,6610.71 U1.35
  Bottom Layer w30: R46.2 S2.2
GPIOF4: P1.2 R50.2 S2.4 U1.155 U4.17 | length 81.6
  Bottom Layer w30: R50.2 S2.4
GPIOF5: P1.3 U1.157 U4.19
GPIOF6: U1.87 U3.1 | length 1031.9
  Top Layer w10: U1.87 11315.67,6319.33 11519,6116 11519,5791 11600,5710 11745,5710 11780,5745 U3.1
GPIOF7: U1.89 U3.4 | length 717.1
  Top Layer w10: U1.89 11630,6207.8 U3.4
GPIOF8: P5.6 U1.28 | length 644.4
  Top Layer w10: P5.6 10046,6406 10046,6466 10328.51,6748.51 U1.28
GPIOF9: P5.4 U1.25 | length 550.8
  Top Layer w10: P5.4 10247.56,6807.56 U1.25
GPIOF10: P5.5 U1.26 | length 595.8
  Top Layer w10: P5.5 9980,6460 10307.88,6787.88 U1.26
GPIOF11: P5.7 U1.29 | length 739.1
  Top Layer w10: P5.7 10020,6240 10060,6280 10060,6445 10343.82,6728.82 U1.29
GPIOF12: P5.3 R48.2 S2.3 U1.22 | length 615.5
  Top Layer w10: P5.3 10206.62,6866.62 U1.22
  Bottom Layer w30: R48.2 S2.3
GPIOF13: P5.2 U1.20 | length 508.8
  Top Layer w10: P5.2 10145.99,6905.99 U1.20
GPIOF14: K4.3 R7.1 U1.140
GPIOG4: U1.90
GPIOG5: U1.91
Net12M_1: 12M.1 C5.1 U4.27
Net12M_2: 12M.2 C4.1 U4.26
NetC3_1: C3.1 R20.1 R21.1 U4.9 URST.1
NetC9_1: C9.1 U5.5
NetC23_1: C23.1 U1.10 | length 391.1
  Top Layer w10: U1.10 10472.84,7102.84 10495,7125 v1(10495,7225)
  Bottom Layer w10: C23.1 10323.39,7225 v1(10495,7225)
NetC26_1: C26.1 U1.11 | length 127.8
  Top Layer w10: v1(10300,7095) 10300,7090 10306.85,7083.15 U1.11
NetC44_2: C44.2 U1.76 X1.1 | length 327.3
  Top Layer w10: X1.1 11099.13,6259.13 U1.76
  Bottom Layer w30: X1.1 C44.2
NetC45_2: C45.2 U1.77 X1.2 | length 319.9
  Top Layer w10: U1.77 11118.82,6241.18 X1.2
  Bottom Layer w30: X1.2 C45.2
NetCAN_1: CAN.1 U3.7 | length 215.7
  Top Layer w10: U3.7 11730,5370 CAN.1
NetCAN_2: CAN.2 U3.6 | length 195
  Top Layer w10: CAN.2 U3.6
NetD1_2: D1.2 R9.2 | length 84.2
  Top Layer w10: D1.2 R9.2
NetD2_2: D2.2 R10.2 | length 84.2
  Top Layer w10: D2.2 R10.2
NetD3_2: D3.2 R11.2 | length 84.2
  Top Layer w10: D3.2 R11.2
NetD4_2: D4.2 R12.2 | length 84.2
  Top Layer w10: D4.2 R12.2
NetD5_2: D5.2 R13.2 | length 84.2
  Top Layer w10: D5.2 R13.2
NetD6_2: D6.2 R14.2 | length 84.2
  Top Layer w10: D6.2 R14.2
NetD7_2: D7.2 R15.2 | length 84.2
  Top Layer w10: D7.2 R15.2
NetD8_2: D8.2 R16.2 | length 84.2
  Top Layer w10: D8.2 R16.2
NetD9_1: D9.1 R21.2 U4.2
NetD9_2: D9.2 U4.1
NetD10_2: D10.2 R25.2
NetD11_2: D11.2 R26.2
NetD12_2: D12.2 R27.2
NetD13_2: D13.2 R28.2
NetD14_2: D14.2 R29.2
NetD15_1: D15.1 R30.2
NetDSPRST_2: DSPRST.2 R8.2
NetJ1_2: J1.2 J1.3 P3.1
NetJ2_2: J2.2 R24.2
NetJ2_3: J2.3 R22.2
NetL3_2: L3.2 U1.162
NetR17_1: R17.1 U4.12
NetR22_1: R22.1 R23.2 U4.6
NetR23_1: R23.1 U4.5
NetR24_1: R24.1 U4.7
NetR26_1: R26.1 U4.29
NetR27_1: R27.1 U4.30
NetR28_1: R28.1 U4.31
NetR29_1: R29.1 U4.32
NetR36_2: R36.2 U1.16 | length 129.3
  Top Layer w10: v1(10300,7000) 10300,6995 10310.27,6984.73 U1.16
NetR45_1: R45.1 S2.8 | length 81.6
  Bottom Layer w30: R45.1 S2.8
NetR47_1: R47.1 S2.7 | length 81.6
  Bottom Layer w30: R47.1 S2.7
NetR49_1: R49.1 S2.6 | length 81.6
  Bottom Layer w30: R49.1 S2.6
NetR51_1: R51.1 S2.5 | length 81.6
  Bottom Layer w30: R51.1 S2.5
NetTP5_1: TP5.1 U4.22
RI_CP: P1.6 U4.16
RTS: P1.4 U4.20
TCLK: JTAG.9 JTAG.11 U1.136
TDI: JTAG.3 U1.131
TDO: JTAG.7 U1.127
TMS: JTAG.1 U1.126
TRST: C10.1 JTAG.2 R31.2 U1.135
USBSCL: P1.10 R18.1 U4.11 U6.6
USBSDA: P1.11 R19.1 U4.10 U6.5
VBUS: D10.1 J2.1 P3.3
VIN: P3.2 SW1.2 SW1.5
X\H\O\L\D\: U1.159
X\H\O\L\D\A\: U1.82
XA0: U1.18
XA1: U1.43
XA2: U1.80
XA3: U1.85
XA4: U1.103
XA5: U1.108
XA6: U1.111
XA7: U1.118
XA8: U1.121
XA9: U1.125
XA10: U1.130
XA11: U1.132
XA12: U1.138
XA13: U1.141
XA14: U1.144
XA15: U1.148
XA16: U1.152
XA17: U1.156
XA18: U1.158
XD0: U1.21
XD1: U1.24
XD2: U1.27
XD3: U1.30
XD4: U1.33
XD5: U1.36
XD6: U1.39
XD7: U1.54
XD8: U1.65
XD9: U1.68
XD10: U1.73
XD11: U1.74
XD12: U1.96
XD13: U1.97
XD14: U1.139
XD15: U1.147
XMP/M\C\: R43.1 R52.2 U1.17 | length 334.5
  Top Layer w10: v1(10100,6930) 10135.04,6965.04 U1.17
XOUT: TP3.1 U1.119
XRD: U1.42
XREADY: U1.161
XRS: C2.1 DSPRST.3 R1.1 U1.160
XRW: U1.51
XWE: U1.84
XZCS01: U1.44
XZCS2: U1.88
XZCS67: U1.133
pads on no net: DSPRST.1 DSPRST.4 J2.5 J2.6 JTAG.6 K1.1 K1.4 K2.1 K2.4 K3.1 K3.4 K4.1 K4.4 SW1.3 SW1.4 U1.66 U1.67 U1.164 U3.5 U3.8 U6.7 URST.2 URST.3

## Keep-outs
Keep-Out Layer:
  the board outline again, w10

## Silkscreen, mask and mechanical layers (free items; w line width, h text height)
Mechanical 1:
  the board outline again, w10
